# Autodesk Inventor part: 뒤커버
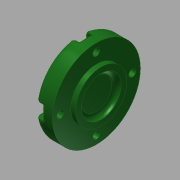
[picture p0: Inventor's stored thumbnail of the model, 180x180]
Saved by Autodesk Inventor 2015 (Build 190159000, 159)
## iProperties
Created: 2015-11
Part Number: 뒤커버
Material: 알루미늄 6061
Document SubType Name: Modeling
Designer: mduedu
Density: 1 g/cm^3
Appearance: 매끄러움 - 짙은 산림 녹색
Author: mduedu
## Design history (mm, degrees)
sketch "스케치1"
  geometry: L1 (-7, 0)-(7, 0); L2 (-7, 0)-(-7, 27.5); L3 (-7, 27.5)-(4, 27.5); L4 (4, 27.5)-(4, 16); L5 (4, 16)-(7, 16); L6 (7, 16)-(7, 0); 2 further points
  constraints: 12 end point, 3 perpendicular, 2 parallel, 1 coincident, 1 horizontal, 1 midpoint
  dimensions: "d0" = 14 distance of L1.start L1.end; "d1" = 55 diameter of L3 L1; "d2" = 3 distance of L4.end L5.end; "d3" = 32 diameter of L5 L1
revolve "회전1" sketch "스케치1" stored, may be unused: angle "d4" = 90 deg
hole "구멍1" diameter "d7" = 25; stored, may be unused: countersink angle "d11" = 90 deg, drill point angle "d13" = 0 deg; dims "d5" = 10, "d6" = 10, "d8" = 6, "d9" = 4, "d10" = 2, "d12" = 3
fillet "모깎기2" dims "d36" = 3
fillet "모깎기3" dims "d37" = 3
sketch "스케치2" dims "d39" = 45
  geometry: C1 r 12.846 at (0, 0) reference; C2 r 24.5 at (0, 0) reference; 6 further points
  constraints: 2 vertical alignment, 1 coincident, 7 other
  dimensions: "d42" = 360 deg dimension on point (0, 0) point (0, 22.5) (derived)
sketch "스케치3"
  geometry: 8 further points
  constraints: 4 coincident
hole "구멍4" sketch "스케치3" at (-22.5, 0), (0, -22.5), (22.5, 0), (0, 22.5) diameter "d44" = 4.5; stored, may be unused: countersink angle "d48" = 90 deg, drill point angle "d50" = 0 deg; dims "d45" = 6, "d46" = 8, "d47" = 4.6, "d49" = 8
sketch "스케치4"
  geometry: L1 (-4, 0)-(-4, -4.708); L2 (4, 0)-(4, -4.708); A1 r 4 centre (0, 0) between (-4, 0) and (4, 0) reference; A2 r 27.5 centre (0, 22.5) between (-4, -4.708) and (4, -4.708) reference; 3 further points
  constraints: 4 end point, 4 point on circle, 2 tangent, 1 parallel, 1 vertical
extrude "돌출1" cut sketch "스케치4" stored distance "d51" = 0; taper "d52" = 0 deg
fillet "모깎기5" dims "d56" = 0.3
fillet "모깎기6" dims "d57" = 1
node "솔리드1"
pattern_circular "원형 패턴1" dims angle "d54" = 360 deg
